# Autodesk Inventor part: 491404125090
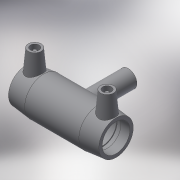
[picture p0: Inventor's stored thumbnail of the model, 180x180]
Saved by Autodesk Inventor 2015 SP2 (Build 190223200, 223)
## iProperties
Created: 2017-06
Part Number: 491404125090
Material: Generic
Description: PLASSON REDUCING TEE 125x90x125
Document SubType Name: Modeling
Designer: KIM
Mass: 57.3761 g
Surface Area: 241.06 cm^2
Volume: 57.3761 cm^3
Density: 1 g/cm^3
Appearance: Default
Author: KIM
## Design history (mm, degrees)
derived "491404.ipt"
feature "Solid1::491404.ipt"
tag "TaggingFeature1"
body "Solid1"
other parameters: "d0" = 382, "d1" = 125, "d2" = 165, "d3" = 86, "d4" = 76.4, "d5" = 148.5, "d6" = 118.75, "d7" = 125, "d8" = 168 deg, "d10" = 34.4, "d11" = 11.46667, "d13" = 382, "d14" = 17.6296, "d17" = 112.5, "d18" = 125, "d19" = 3.52592, "d20" = 168 deg, "d22" = 153.45, "d23" = 165, "d25" = 135 deg, "d26" = 267.4, "d29" = 88, "d30" = 15, "d31" = 152.8, "d34" = 5 deg, "d35" = 15, "d39" = 5 deg, "d41" = 4, "d42" = 14, "d43" = 0, "d45" = 4, "d46" = 6, "d47" = 0, "d48" = -161, "d51" = 0, "d52" = 72, "d54" = 0, "d55" = 148.5, "d56" = 165, "d57" = 133.7, "d58" = 135 deg, "d59" = 86, "d60" = 86, "d61" = 135 deg, "d62" = 161, "d72" = 173.81, "d73" = 86.905, "d74" = -161, "d75" = 94.5, "d77" = 0, "d78" = 72, "d80" = 0, "d82" = 78.5, "d83" = 0, "d84" = 3, "d85" = 0, "d86" = 28.66667, "d87" = 150.381, "d88" = 11.46667, "d89" = 3, "d90" = 0, "d_" = 125, "L_" = 382, "L_1" = 86, "D_" = 165, "A_" = 88, "d_2" = 12, "H_" = 161
